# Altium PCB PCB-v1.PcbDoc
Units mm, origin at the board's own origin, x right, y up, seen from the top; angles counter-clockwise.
Board outline 50 x 50 mm, 2 copper layers (Top Layer, Bottom Layer); 47 components, 33 nets, 206 pads, 0 vias.
Unrouted connection lines stored in the file: 119.
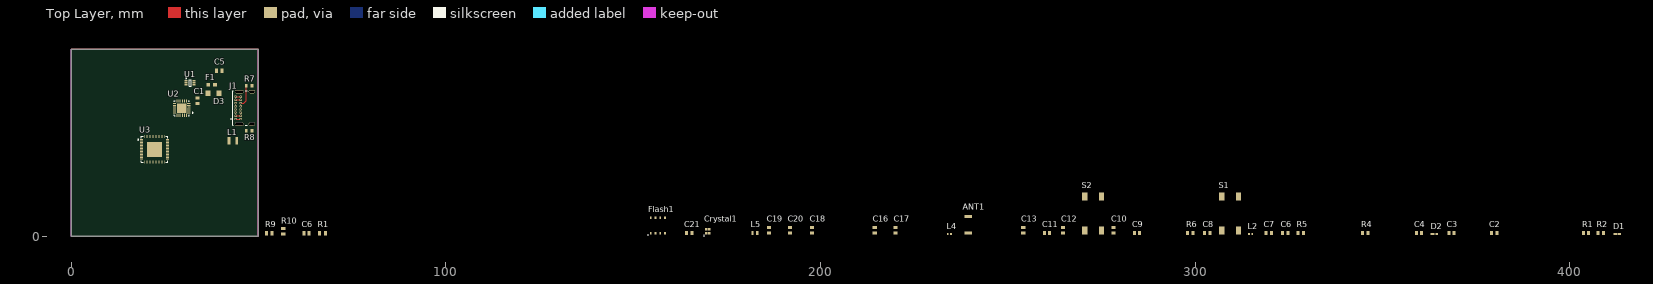
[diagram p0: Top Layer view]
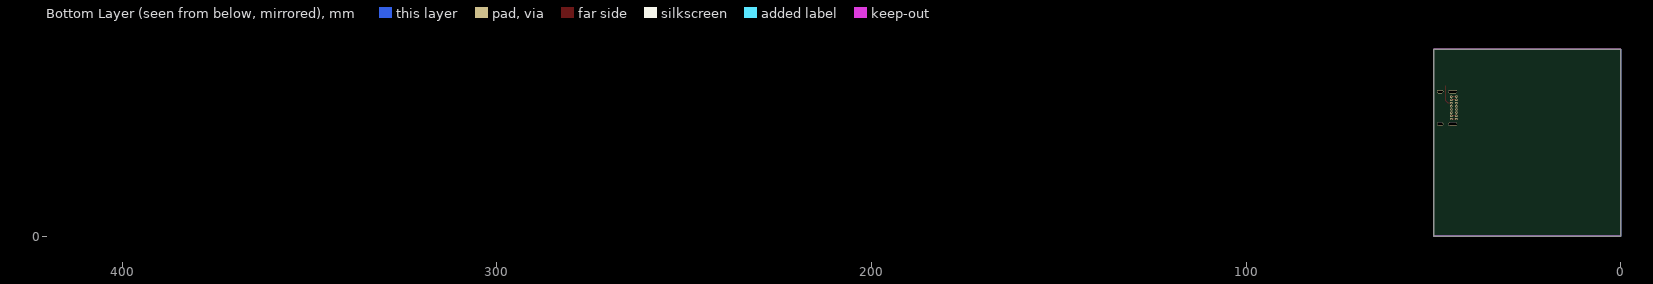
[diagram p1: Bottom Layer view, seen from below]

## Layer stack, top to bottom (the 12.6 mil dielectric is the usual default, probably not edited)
Top Solder: solder mask 0.0102, Solder Resist, Dk 3.5
Top Layer: signal copper 0.0356
Dielectric 1: dielectric 0.32, FR-4, Dk 4.8
Bottom Layer: signal copper 0.0356
Bottom Solder: solder mask 0.0102, Solder Resist, Dk 3.5

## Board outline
0,0 50,0 50,50 0,50

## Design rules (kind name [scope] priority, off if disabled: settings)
BoardOutlineClearance [All] p1: gap=0.2 ignorepadtopadclearanceinfootprint=FALSE
Clearance [All] p1: gap=0.127 ignorepadtopadclearanceinfootprint=TRUE except(0.254: Arc-Hole Track-Hole SMDPad-Hole THPad-Hole Via-Hole Fill-Hole Poly-Hole Region-Hole Text-Hole)
ComponentClearance [All] p1: gap=0.127 collisioncheckmode=3 verticalgap=0.127 showdistances=TRUE
DiffPairsRouting [All] p1: maxlimit=0.254 minlimit=0.127 mostfreqgap=0.127 toplayer_minwidth=0.127 toplayer_maxwidth=25.4 toplayer_prefwidth=0.127 bottomlayer_minwidth=0.127 bottomlayer_maxwidth=25.4 bottomlayer_prefwidth=0.127 maxuncoupledlength=12.7
Height [All] p1: minheight=0 maxheight=1816.048 prefheight=12.7
HoleSize [All] p1: absolutevalues=TRUE maxlimit=6.3 minlimit=0.3 maxpercent=80.000 minpercent=20.000
HoleToHoleClearance [All] p1: gap=0.254 allowstackedmicrovias=FALSE
MinimumAnnularRing [All] p1: minimumring=0.152
MinimumSolderMaskSliver [All] p1: minsoldermaskwidth=0.152
PlaneClearance [All] p1: clearance=0.127
PlaneConnect PlaneConnectPowerPads [InPadClass('PowerPads')] p1: planeconnectstyle=Direct reliefexpansion=0.508 reliefentries=4 reliefconductorwidth=0.254 reliefairgap=0.254
PlaneConnect [All] p2: pad.planeconnectstyle=Relief pad.reliefexpansion=0.3 pad.reliefentries=4 pad.reliefconductorwidth=0.127 pad.reliefairgap=0.127 via.planeconnectstyle=Direct via.reliefexpansion=0.3 via.reliefentries=4 via.reliefconductorwidth=0.127 via.reliefairgap=0.127
PolygonConnect PolygonConnectPowerPads [All vs (InPadClass('PowerPads'))] p1: connectstyle=Direct reliefconductorwidth=0.254 reliefentries=4 polygonreliefangle="90 Angle" airgapwidth=0.254
PolygonConnect [All] p2: thpad.connectstyle=Relief thpad.reliefconductorwidth=0.127 thpad.reliefentries=4 thpad.polygonreliefangle="90 Angle" thpad.airgapwidth=0.127 smdpad.connectstyle=Relief smdpad.reliefconductorwidth=0.127 smdpad.reliefentries=4 smdpad.polygonreliefangle="90 Angle" smdpad.airgapwidth=0.127 via.connectstyle=Direct via.reliefconductorwidth=0.127 via.reliefentries=4 via.polygonreliefangle="90 Angle" via.airgapwidth=0.127
RoutingVias [All] p1: holewidth=0.3 width=0.6 viastyle="Through Hole" minholewidth=0.3 minwidth=0.6 maxholewidth=0.6 maxwidth=6.6
SilkToSilkClearance [All] p1: silktosilkclearance=0.127
SilkToSolderMaskClearance [IsPad] p1: minsilkscreentomaskgap=0.127 clearancetoexposedcopper=TRUE
SolderMaskExpansion [All] p1: expansion=0.051 istentingtop=FALSE
SupplyNets "Schematic Supply Nets_4" [InNet('+3.3V')] p1: voltage=0.000
SupplyNets "Schematic Supply Nets_1" [InNet('GND')] p2: voltage=0.000
SupplyNets "Schematic Supply Nets" [InNet('+3.3')] p3: voltage=0.000
UnRoutedNet [All] p1: checkbadconnections=TRUE
Width Width_10mil [All] p1: maxlimit=25.4 minlimit=0.254 preferedwidth=0.254 minimp=50.000000 maximp=50.000000 favimp=50.000000
Width Width_6mil [All] p2: maxlimit=25.4 minlimit=0.152 preferedwidth=0.152 minimp=50.000000 maximp=50.000000 favimp=50.000000
Width Power_20mil [All] p3: maxlimit=25.4 minlimit=0.508 preferedwidth=0.508 minimp=50.000000 maximp=50.000000 favimp=50.000000
Width Power_12mil [All] p4: maxlimit=25.4 minlimit=0.305 preferedwidth=0.305 minimp=50.000000 maximp=50.000000 favimp=50.000000
Width Width_5mil [All] p5: maxlimit=25.4 minlimit=0.127 preferedwidth=0.127 minimp=50.000000 maximp=50.000000 favimp=50.000000
19 further rules are at their usual default settings.

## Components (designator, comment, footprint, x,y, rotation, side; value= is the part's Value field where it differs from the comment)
ANT1 "PCB_ANT" "Antenne // RFANT5220110A0T" 239.395,3.175 r90 top
C1 "1µF" CAP_General_0603 33.75,36.2 r90 top
C2 "10µF" CAP_General_0603 379.857,0.889 r0 top
C3 "10pF" CAP_General_0603 368.427,0.889 r0 top
C4 "1µF" CAP_General_0603 359.791,0.889 r0 top
C5 "4.7µF" CAP_General_0603 39.5,44.25 r0 top
C6 "1µF" CAP_General_0603 62.85,0.85 r0 top
C6 "0.1µF" CAP_General_0603 324.104,0.889 r0 top
C7 "1µF" CAP_General_0603 319.659,0.889 r0 top
C8 "0.1µF" CAP_General_0603 303.276,0.889 r0 top
C9 "0.1µF" CAP_General_0603 284.48,0.889 r0 top
C10 "0.1µF" CAP_General_0603 278.257,1.651 r90 top
C11 "1µF" CAP_General_0603 260.477,0.889 r0 top
C12 "10nF" CAP_General_0603 264.795,1.651 r90 top
C13 "0.1µF" CAP_General_0603 254.127,1.651 r90 top
C16 "1pF" CAP_General_0603 214.503,1.651 r90 top
C17 "1pF" CAP_General_0603 220.091,1.651 r90 top
C18 "10pF" CAP_General_0603 197.739,1.651 r90 top
C19 "0.1µF" CAP_General_0603 186.309,1.651 r90 top
C20 "10µF" CAP_General_0603 191.897,1.651 r90 top
C21 "10pF" CAP_General_0603 164.973,0.889 r0 top
Crystal1 "Crystal" "Crystal // ECS­400­8­47B2­CKM­TR" 169.926,1.397 r90 top
D1 "LED" "LED // KRDELPS1.22-UIVG-46-H3Q4-XX" 412.75,0.635 r0 top
D2 "LED" "LED // KRDELPS1.22-UIVG-46-H3Q4-XX" 363.982,0.635 r0 top
D3 "ESD diode 5V" "ESD diode 5V // SMF5.0A" 38,38.25 r0 top
F1 "Fuse" "Fuse // 0603L050SLYR" 37.5,40.5 r180 top
Flash1 "128 Mbit NOR Flash" "128 Mbit NOR Flash // AT25QF128A-MHB-T" 156.591,2.921 r90 top
J1 "USB4085-GF-A" "USB-C connector // USB4085-GF-A" 47.915,34.325 r90 top
L1 "1µH" "Inductor 1µH // MLP2520H1R0MT0S1" 43.2,25.5 r0 top
L2 "2nH" "Inductor 2nH // MLG1005S2N0BTD25" 314.833,0.635 r0 top
L4 "2nH" "Inductor 2nH // MLG1005S2N0BTD25" 234.442,0.635 r0 top
L5 "24nH" "Inductor 24 nH // 36501J24NJTDG" 182.499,0.889 r0 top
R1 "100K" RES_100K_0603 67.1,0.85 r0 top
R1 "453K" RES_453K_0603 404.368,0.889 r0 top
R2 "499R" RES_499R_0603 408.305,0.889 r0 top
R4 "499R" RES_499R_0603 345.44,0.889 r0 top
R5 "10K" RES_10K_0603_1 328.168,0.889 r0 top
R6 "10K" RES_10K_0603_1 298.704,0.889 r0 top
R7 "5.1K" RES_5.1K_0603 47.5,40.25 r180 top
R8 "5.1K" RES_5.1K_0603 47.5,28.25 r180 top
R9 "10K" RES_10K_0603_1 52.85,0.85 r0 top
R10 "10K" RES_10K_0603_1 56.6,1.35 r90 top
S1 "Drukknop" "Tactile Switches // FSM4JSMAATR" 309.372,6.096 r0 top
S2 "Drukknop" "Tactile Switches // FSM4JSMAATR" 272.796,6.096 r0 top
U1 "Convertor 5V-3.3V" "CONVERTOR // TLV62569APDRLR" 31.75,41 r0 top
U2 "CP2102N-A02-GQFN24R" "USB Bridge // CP2102N-A02-GQFN24R" 29.5,34.25 r180 top
U3 "ESP32-S3R8" FP-ESP32-S3R8 22.25,23.25 r0 top

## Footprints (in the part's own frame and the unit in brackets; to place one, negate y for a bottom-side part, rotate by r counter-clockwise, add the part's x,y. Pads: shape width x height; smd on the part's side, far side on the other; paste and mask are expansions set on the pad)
"128 Mbit NOR Flash // AT25QF128A-MHB-T" [mm]
  rrect50% 0.7x0.45 smd: 1(-2.05,1.905)
  rect 0.7x0.45 smd: 2(-2.05,0.635) 3(-2.05,-0.635) 4(-2.05,-1.905) 5(2.05,-1.905) 6(2.05,-0.635) 7(2.05,0.635) 8(2.05,1.905)
  silkscreen extent -2.64,2.55 -2.48,2.71
"Antenne // RFANT5220110A0T" [mm]
  rect 0.8x2 smd: 1(-2.2,0) 2(2.2,0)
CAP_General_0603 [mm] "Chip Capacitor, 2-Leads, Body 1,60x0,80mm, IPC Medium Density"
  rect 0.8x1.1 smd: 1(-0.7,0) 2(0.7,0)
  body extent -0.85,-0.45 0.85,0.45, height 0.7
"CONVERTOR // TLV62569APDRLR" [mm] "SOT23, 6-Leads, Body 1,60x2,15mm, Pitch 0,50mm, IPC Medium Density"
  rect 0.85x0.4 smd: 1(-1.075,0.5) 2(-1.075,0) 3(-1.075,-0.5) 4(1.075,-0.5) 5(1.075,0) 6(1.075,0.5)
  silkscreen extent -1.2,-0.85 0.25,1.37, body extent -0.65,-0.85 0.65,0.85, height 0.6
"Crystal // ECS­400­8­47B2­CKM­TR" [mm] "40 MHz Crystal"
  rect 0.75x0.65 smd: 1(-0.525,0.375) 2(-0.525,-0.375) 3(0.525,-0.375) 4(0.525,0.375)
  silkscreen extent -1.28,0.92 -1.12,1.08
"ESD diode 5V // SMF5.0A" [mm]
  rect 1.3x1.4 smd: 1(-1.45,0) 2(1.45,0)
FP-ESP32-S3R8 [mm]
  rect 0.818x0.192 smd paste+0 mask+0: 1(-3.427,2.6)
  rrect100% 0.818x0.192 smd paste+0 mask+0: 2(-3.427,2.2) 3(-3.427,1.8) 4(-3.427,1.4) 5(-3.427,1) 6(-3.427,0.6) 7(-3.427,0.2) 8(-3.427,-0.2) 9(-3.427,-0.6) 10(-3.427,-1) 11(-3.427,-1.4) 12(-3.427,-1.8) 13(-3.427,-2.2) 14(-3.427,-2.6) 29(3.427,-2.6) 30(3.427,-2.2) 31(3.427,-1.8) 32(3.427,-1.4) 33(3.427,-1) 34(3.427,-0.6) 35(3.427,-0.2) 36(3.427,0.2) 37(3.427,0.6) 38(3.427,1) 39(3.427,1.4) 40(3.427,1.8) 41(3.427,2.2) 42(3.427,2.6)
  rrect100% 0.192x0.818 smd paste+0 mask+0: 15(-2.6,-3.427) 16(-2.2,-3.427) 17(-1.8,-3.427) 18(-1.4,-3.427) 19(-1,-3.427) 20(-0.6,-3.427) 21(-0.2,-3.427) 22(0.2,-3.427) 23(0.6,-3.427) 24(1,-3.427) 25(1.4,-3.427) 26(1.8,-3.427) 27(2.2,-3.427) 28(2.6,-3.427) 43(2.6,3.427) 44(2.2,3.427) 45(1.8,3.427) 46(1.4,3.427) 47(1,3.427) 48(0.6,3.427) 49(0.2,3.427) 50(-0.2,3.427) 51(-0.6,3.427) 52(-1,3.427) 53(-1.4,3.427) 54(-1.8,3.427) 55(-2.2,3.427) 56(-2.6,3.427)
  rect 4.05x4.05 smd paste-1000 mask+0: 57(0,0)
  silkscreen extent -4.51,-3.5 3.5,3.5, body extent -4.1,-4.09 4.07,4.09, height 0.25
"Fuse // 0603L050SLYR" [mm]
  rect 1x1 smd: 1(-0.9,0) 2(0.9,0)
"Inductor 1µH // MLP2520H1R0MT0S1" [mm]
  rect 0.7x2 smd: 1(-1.05,0) 2(1.05,0)
"Inductor 2nH // MLG1005S2N0BTD25" [mm]
  rect 0.5x0.5 smd: 1(-0.45,0) 2(0.45,0)
"Inductor 24 nH // 36501J24NJTDG" [mm]
  rect 0.64x1.02 smd: 1(-0.64,0) 2(0.64,0)
"LED // KRDELPS1.22-UIVG-46-H3Q4-XX" [mm]
  rect 1.05x0.5 smd: 1(-0.557,0)
  rect 0.7x0.5 smd: 2(0.557,0)
RES_5.1K_0603 [mm] "Chip Resistor, 2-Leads, Body 1,60x0,80mm, IPC Medium Density"
  rect 0.75x1 smd: 1(-0.75,0) 2(0.75,0)
  body extent -0.9,-0.5 0.9,0.5, height 0.5
RES_10K_0603_1 [mm] "Chip Resistor, 2-Leads, Body 1,55x0,80mm, IPC Medium Density"
  rect 0.8x1.1 smd: 1(-0.75,0) 2(0.75,0)
  body extent -0.83,-0.45 0.82,0.45, height 0.55
RES_100K_0603 [mm] "Chip Resistor, 2-Leads, Body 1,60x0,80mm, IPC Medium Density"
  rect 0.8x1.1 smd: 1(-0.75,0) 2(0.75,0)
  body extent -0.9,-0.5 0.9,0.5, height 0.65
RES_453K_0603 [mm] "Chip Resistor, 2-Leads, Body 1,55x0,80mm, IPC Medium Density"
  rect 0.8x1.1 smd: 1(-0.7,0) 2(0.7,0)
  body extent -0.83,-0.45 0.82,0.45, height 0.55
RES_499R_0603 [mm] "Chip Resistor, 2-Leads, Body 1,55x0,85mm, IPC Medium Density"
  rect 0.8x1.1 smd: 1(-0.7,0) 2(0.7,0)
  body extent -0.8,-0.48 0.8,0.47, height 0.55
"Tactile Switches // FSM4JSMAATR" [mm]
  rect 1.4x2.1 smd: 1(2.23,4.55) 2(2.23,-4.55) 3(-2.23,4.55) 4(-2.23,-4.55)
"USB Bridge // CP2102N-A02-GQFN24R" [mm]
  rect 0.91x0.239 smd paste+0 mask+0: 1(-1.901,1.25)
  rrect100% 0.91x0.239 smd paste+0 mask+0: 2(-1.901,0.75) 3(-1.901,0.25) 4(-1.901,-0.25) 5(-1.901,-0.75) 6(-1.901,-1.25) 13(1.901,-1.25) 14(1.901,-0.75) 15(1.901,-0.25) 16(1.901,0.25) 17(1.901,0.75) 18(1.901,1.25)
  rrect100% 0.239x0.91 smd paste+0 mask+0: 7(-1.25,-1.901) 8(-0.75,-1.901) 9(-0.25,-1.901) 10(0.25,-1.901) 11(0.75,-1.901) 12(1.25,-1.901) 19(1.25,1.901) 20(0.75,1.901) 21(0.25,1.901) 22(-0.25,1.901) 23(-0.75,1.901) 24(-1.25,1.901)
  rect 2.55x2.55 smd paste-1000 mask+0: 25(0,0)
  silkscreen extent -3.03,-2 2,2, body extent -2.61,-2.61 2.61,2.61, height 0.25
"USB-C connector // USB4085-GF-A" [mm]
  rrect100% 0.9x2.4 hole 2.1 slot 0.6 at 0 deg paste-2539.97 mask+0: 1(-4.325,3.045) 2(4.325,3.045)
  rrect100% 0.9x1.7 hole 1.4 slot 0.6 at 0 deg paste-2539.97 mask+0: 3(-4.325,-0.335) 4(4.325,-0.335)
  round 0.65 hole 0.4 paste-2539.97 mask+0: A1(-2.975,4.025) A4(-2.125,4.025) A5(-1.275,4.025) A6(-0.425,4.025) A7(0.425,4.025) A8(1.275,4.025) A9(2.125,4.025) A12(2.975,4.025) B1(2.975,2.675) B4(2.125,2.675) B5(1.275,2.675) B6(0.425,2.675) B7(-0.425,2.675) B8(-1.275,2.675) B9(-2.125,2.675) B12(-2.975,2.675)
  silkscreen extent -4.57,0.89 4.57,5.37, body extent -4.87,-4.83 4.87,4.83, height 0.25

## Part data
ANT1: library part "Antenne // RFANT5220110A0T"
C1 C2 C3 C4 C5 C6 C6 C7 C8 C9 C10 C11 C12 C13 C16 C17 C18 C19 C20 C21: library part CAP_General_0603, "Capacitor SMD 0603 ?pF"
Crystal1: library part "Crystal // ECS­400­8­47B2­CKM­TR"
D1 D2: library part "LED // KRDELPS1.22-UIVG-46-H3Q4-XX"
D3: library part "ESD diode 5V // SMF5.0A"
F1: library part "Fuse // 0603L050SLYR"
Flash1: library part "128 Mbit NOR Flash // AT25QF128A-MHB-T"
J1: library part "USB-C connector // USB4085-GF-A", "CONN RCPT USB2.0 TYPE C 24POS RA"
L1: library part "Inductor 1µH // MLP2520H1R0MT0S1"
L2 L4: library part "Inductor 2nH // MLG1005S2N0BTD25"
L5: library part "Inductor 24 nH // 36501J24NJTDG"
R1: library part RES_100K_0603, "Resistor SMD 0603 100K"
R1: library part RES_453K_0603, "Resistor SMD 0603 453K"
R2 R4: library part RES_499R_0603, "Resistor SMD 0603 499R"
R5 R6 R7 R8 R9 R10: library part RES_10K_0603_1, "Resistor SMD 0603 10K"
S1 S2: library part "Tactile Switches // FSM4JSMAATR"
U1: library part "Convertor // TLV62569APDRLR"
U2: library part "USB Bridge // CP2102N-A02-GQFN24R", "IC USB TO UART BRIDGE QFN24", Ambient Temperature Range High=85°C, Manufacturer Lifecycle Status="FULL PRODUCTION", Max Junction Temperature (Tj)=105°C, Max Supply Voltage=3.6V, Min Operating Temperature=-40°C, Min Supply Voltage=1.71V
U3: library part ESP32-S3, "ESP32-S3R8 RF System on a Chip - SoC SMD IC, Dual-Core MCU, Wi-Fi 2.4G BLE 5.0 Combo"

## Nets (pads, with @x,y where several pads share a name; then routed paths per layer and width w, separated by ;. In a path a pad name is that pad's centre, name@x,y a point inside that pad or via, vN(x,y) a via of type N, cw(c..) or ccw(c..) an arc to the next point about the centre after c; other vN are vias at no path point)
+3.3: C6.1@62.15,0.85 C7.2 L1.2 R1.2@405.068,0.889 U2.5
+3.3V: C2.2 C4.2 C6.2@324.804,0.889 C9.1 C10.2 C11.2 C12.2 L2.1 R2.1 R5.1 R6.2 U3.20 U3.46 U3.55 U3.56
+5V: C3.2 C5.2 D3.1 F1.2 U1.3 U1.5 U2.7 U2.8
GND: C1.2 C2.1 C3.1 C4.1 C5.1 C6.1@323.404,0.889 C6.2@63.55,0.85 C7.1 C8.1 C9.2 C10.1 C11.1 C12.1 C13.1 C18.2 C19.1 C20.1 C21.2 Crystal1.2 Crystal1.4 D1.2 D2.2 D3.2 Flash1.4 J1.1 J1.2 J1.3 J1.4 J1.A1 J1.A12 J1.B1 J1.B12 R1.1@66.35,0.85 R7.1 R8.1 R9.1 R10.1 S1.3 S1.4 S2.3 S2.4 U1.2 U2.2 U2.25 U3.57 | length 2.7
  Top Layer w0.254: J1.A1 J1.B12 ; J1.A12 J1.B1
NetANT1_1: ANT1.1 C16.2 L4.1
NetANT1_2: ANT1.2 C16.1 C17.1
NetC1_1: C1.1 U2.6
NetC8_2: C8.2 L2.2 U3.2 U3.3
NetC13_2: C13.2 R6.1 S2.1 S2.2 U3.4
NetC17_2: C17.2 L4.2 U3.1
NetC18_1: C18.1 Crystal1.1 L5.1
NetC19_2: C19.2 C20.2 Flash1.8 U3.29
NetC21_1: C21.1 Crystal1.3 U3.53
NetD1_1: D1.1 R2.2
NetD2_1: D2.1 R4.2
NetFlash1_1: Flash1.1 U3.32
NetFlash1_2: Flash1.2 U3.34
NetFlash1_3: Flash1.3 U3.31
NetFlash1_5: Flash1.5 U3.35
NetFlash1_6: Flash1.6 U3.33
NetFlash1_7: Flash1.7 U3.30
NetJ1_A5: J1.A5 R9.2 R10.2
NetJ1_A6: J1.A6 J1.B6 U2.3
NetJ1_A7: J1.A7 J1.B7 U2.4
NetJ1_B5: J1.B5 R7.2 R8.2 | length 5.8
  Top Layer w0.254: J1.B5 46.1,35.6 46.75,36.25 R7.2
NetL1_1: L1.1 U1.4
NetL5_2: L5.2 U3.54
NetR1_1: R1.1@403.668,0.889 R1.2@67.85,0.85 U1.1
NetR4_1: R4.1 U3.7
NetR5_2: R5.2 S1.1 S1.2 U3.5
NetU2_20: U2.20 U3.49
NetU2_21: U2.21 U3.50
VBus: F1.1 J1.A4 J1.A9 J1.B4 J1.B9 | length 2.7
  Top Layer w0.254: J1.A4 J1.B9 ; J1.A9 J1.B4
pads on no net: J1.A8 J1.B8 U1.6 U2.1 U2.9 U2.10 U2.11 U2.12 U2.13 U2.14 U2.15 U2.16 U2.17 U2.18 U2.19 U2.22 U2.23 U2.24 U3.6 U3.8 U3.9 U3.10 U3.11 U3.12 U3.13 U3.14 U3.15 U3.16 U3.17 U3.18 U3.19 U3.21 U3.22 U3.23 U3.24 U3.25 U3.26 U3.27 U3.28 U3.36 U3.37 U3.38 U3.39 U3.40 U3.41 U3.42 U3.43 U3.44 U3.45 U3.47 U3.48 U3.51 U3.52

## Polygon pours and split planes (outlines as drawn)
no net on Top Layer "NONET_L01_P000" (solid, remove dead copper, shelved, pour order 0): 0,0 50,0 50,50 0,50
no net on Bottom Layer "NONET_L02_P001" (solid, remove dead copper, shelved, pour order 1): 0,0 50,0 50,50 0,50

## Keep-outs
Keep-Out Layer:
  the board outline again, w0.05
